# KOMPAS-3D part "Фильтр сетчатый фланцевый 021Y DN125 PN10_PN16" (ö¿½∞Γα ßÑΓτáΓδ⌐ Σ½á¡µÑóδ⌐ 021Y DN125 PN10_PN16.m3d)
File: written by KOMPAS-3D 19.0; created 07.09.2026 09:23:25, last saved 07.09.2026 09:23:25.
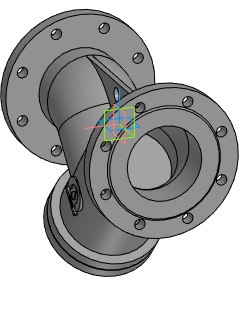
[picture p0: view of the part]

Document properties: Автор: Энергия; Полное имя файла: Z:\3.Личные\sachek\Dendor\_3D для проектировщиков\8.3 Фильтр сетчатый 021Y\021Y_STP\Фильтр сетчатый фланцевый 021Y DN125 PN10_PN16.m3d

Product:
- Part/product: Фильтр сетчатый фланцевый 021Y DN125 PN10_PN16

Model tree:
1. Операция без истории:1  (labels: Фильтр сетчатый фланцевый 021Y DN125 PN10_PN16)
